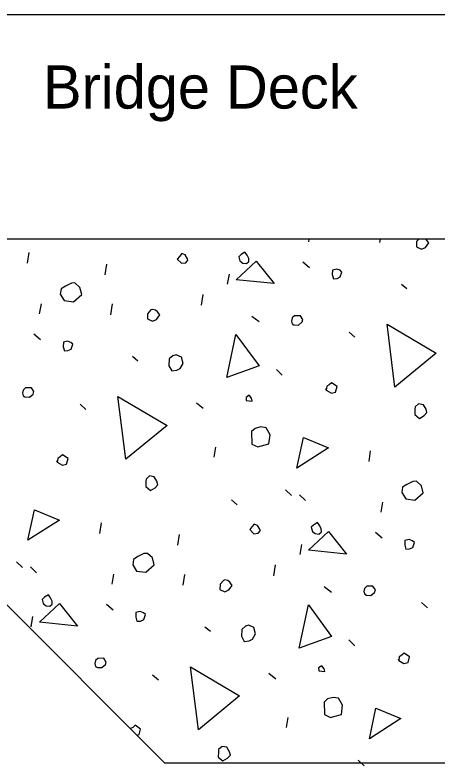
# Model space of a CAD drawing. Extents: x 112544 to 112597.1, y 111084 to 111107.1.
# Drawn here: x 112566.094 to 112567.572, y 111102.745 to 111105.363 of the extents above; entities that cross this region are included whole.
import ezdxf

# ---------------------------------------------------------------- set-up
doc = ezdxf.new("R2010")
doc.units = 0
for name, color, linetype in [('ActivePts-ConstElements', 7, 'Continuous'), ('Miscellaneous', 7, 'Continuous'), ('SupstrConc', 7, 'Continuous'), ('TextStructures', 7, 'Continuous')]:
    doc.layers.add(name, color=color, linetype=linetype)

msp = doc.modelspace()

# ---------------------------------------------------------------- linework, layer by layer
at = {"layer": 'ActivePts-ConstElements'}
msp.add_lwpolyline([(112543.9918, 111085.9039), (112574.7797, 111085.9039), (112574.7797, 111105.3634), (112543.9918, 111105.3634)], close=True, dxfattribs=at)
at = {"layer": 'Miscellaneous'}
for p, q in [((112567.1223, 111104.5697), (112567.1239, 111104.5786)), ((112567.3716, 111104.5666), (112567.3734, 111104.5786)), ((112566.1382, 111104.4949), (112566.1436, 111104.5326)), ((112567.1023, 111104.4996), (112567.1257, 111104.48)), ((112566.4105, 111104.454), (112566.416, 111104.4917)), ((112566.8386, 111104.4212), (112566.8447, 111104.4565)), ((112567.4469, 111104.4211), (112567.4665, 111104.4057)), ((112566.7471, 111104.3475), (112566.7525, 111104.3852)), ((112566.1806, 111104.3174), (112566.1866, 111104.3526)), ((112566.4299, 111104.3143), (112566.4353, 111104.352)), ((112566.923, 111104.3092), (112566.9488, 111104.2903)), ((112566.1605, 111104.2473), (112566.1839, 111104.2277)), ((112567.2641, 111104.2531), (112567.2844, 111104.2353)), ((112566.5051, 111104.1688), (112566.5247, 111104.1534)), ((112567.0092, 111104.1227), (112567.0301, 111104.1024)), ((112566.3223, 111104.0008), (112566.3427, 111103.9829)), ((112566.7298, 111104.0064), (112566.7531, 111103.9868)), ((112566.7912, 111103.8158), (112566.7973, 111103.8511)), ((112567.3336, 111103.8007), (112567.339, 111103.8384)), ((112567.0417, 111103.7018), (112567.0627, 111103.6815)), ((112567.0906, 111103.6838), (112567.1115, 111103.6635)), ((112566.8519, 111103.6664), (112566.8722, 111103.6486)), ((112567.376, 111103.6231), (112567.3821, 111103.6584)), ((112566.3918, 111103.5483), (112566.3972, 111103.586)), ((112567.3559, 111103.553), (112567.3793, 111103.5334)), ((112566.6642, 111103.5074), (112566.6696, 111103.5451)), ((112567.0923, 111103.4746), (112567.0983, 111103.5099)), ((112566.1, 111103.4494), (112566.1209, 111103.4292)), ((112566.1488, 111103.4315), (112566.1697, 111103.4112)), ((112567.0007, 111103.4009), (112567.0061, 111103.4386)), ((112566.4342, 111103.3708), (112566.4403, 111103.406)), ((112566.6835, 111103.3677), (112566.6889, 111103.4054)), ((112567.1766, 111103.3626), (112567.2024, 111103.3437)), ((112566.4142, 111103.3007), (112566.4375, 111103.2811)), ((112567.5178, 111103.3065), (112567.5381, 111103.2887)), ((112566.1505, 111103.2223), (112566.1566, 111103.2575)), ((112566.7587, 111103.2222), (112566.7784, 111103.2068)), ((112567.2628, 111103.1761), (112567.2838, 111103.1558)), ((112566.576, 111103.0542), (112566.5963, 111103.0363)), ((112566.9834, 111103.0598), (112567.0068, 111103.0402)), ((112567.0448, 111102.8692), (112567.0509, 111102.9045)), ((112567.2954, 111102.7552), (112567.3163, 111102.7349))]:
    msp.add_line(p, q, dxfattribs=at)
for points in [[(112567.5001, 111104.57), (112567.4998, 111104.5518), (112567.5176, 111104.5436), (112567.5314, 111104.5499), (112567.5427, 111104.5659), (112567.5346, 111104.5767), (112567.5324, 111104.5786)], [(112567.5077, 111104.5786), (112567.5001, 111104.57)], [(112566.6625, 111104.5086), (112566.6767, 111104.4943), (112566.6918, 111104.4958), (112566.6995, 111104.5056), (112566.6982, 111104.5104), (112566.6895, 111104.5236), (112566.6779, 111104.5283), (112566.6702, 111104.5184), (112566.6625, 111104.5086)], [(112566.8815, 111104.5026), (112566.8913, 111104.4949), (112566.9047, 111104.4933), (112566.9131, 111104.5007), (112566.9129, 111104.511), (112566.9073, 111104.5224), (112566.8992, 111104.5332), (112566.886, 111104.5245), (112566.8776, 111104.5171), (112566.8815, 111104.5026)], [(112566.8681, 111104.4369), (112566.9385, 111104.5023), (112567.0011, 111104.4233), (112566.8681, 111104.4369)], [(112567.2049, 111104.4547), (112567.2088, 111104.4402), (112567.2215, 111104.441), (112567.233, 111104.4467), (112567.2387, 111104.4637), (112567.232, 111104.4697), (112567.2204, 111104.4743), (112567.2059, 111104.4705), (112567.2049, 111104.4547)], [(112566.2528, 111104.3859), (112566.2665, 111104.3637), (112566.2987, 111104.3594), (112566.328, 111104.3853), (112566.3215, 111104.4095), (112566.3043, 111104.4256), (112566.2916, 111104.4248), (112566.2711, 111104.4141), (112566.2555, 111104.4047), (112566.2528, 111104.3859)], [(112566.5584, 111104.3177), (112566.5581, 111104.2995), (112566.5758, 111104.2913), (112566.5896, 111104.2976), (112566.6009, 111104.3135), (112566.5928, 111104.3243), (112566.586, 111104.3303), (112566.5751, 111104.3325), (112566.5703, 111104.3312), (112566.5584, 111104.3177)], [(112567.0647, 111104.2825), (112567.0708, 111104.279), (112567.0866, 111104.278), (112567.0992, 111104.2892), (112567.1021, 111104.2977), (112567.0933, 111104.3109), (112567.0727, 111104.3105), (112567.0644, 111104.3031), (112567.0621, 111104.2922), (112567.0647, 111104.2825)], [(112567.4244, 111104.0605), (112567.3965, 111104.2808), (112567.5686, 111104.1794), (112567.4244, 111104.0605)], [(112566.8356, 111104.0943), (112566.8676, 111104.2452), (112566.9489, 111104.135), (112566.8356, 111104.0943)], [(112566.2632, 111104.2023), (112566.267, 111104.1878), (112566.2798, 111104.1887), (112566.2912, 111104.1943), (112566.297, 111104.2114), (112566.2902, 111104.2173), (112566.2786, 111104.222), (112566.2641, 111104.2181), (112566.2632, 111104.2023)], [(112566.6344, 111104.1594), (112566.633, 111104.1358), (112566.643, 111104.1177), (112566.6605, 111104.1199), (112566.672, 111104.1255), (112566.6826, 111104.1439), (112566.6767, 111104.1656), (112566.659, 111104.1738), (112566.647, 111104.1706), (112566.6344, 111104.1594)], [(112567.1838, 111104.0504), (112567.2022, 111104.0398), (112567.2167, 111104.0437), (112567.2218, 111104.0632), (112567.2028, 111104.0762), (112567.1944, 111104.0688), (112567.1854, 111104.0638), (112567.1838, 111104.0504), (112567.1825, 111104.0553)], [(112566.1229, 111104.0302), (112566.1291, 111104.0266), (112566.1448, 111104.0257), (112566.1574, 111104.0368), (112566.1603, 111104.0453), (112566.1516, 111104.0585), (112566.131, 111104.0582), (112566.1226, 111104.0508), (112566.1203, 111104.0398), (112566.1229, 111104.0302)], [(112566.4826, 111103.8082), (112566.4547, 111104.0285), (112566.6268, 111103.9271), (112566.4826, 111103.8082)], [(112566.9037, 111104.0142), (112566.9249, 111104.0121), (112566.9223, 111104.0218), (112566.9143, 111104.0326), (112566.9035, 111104.0245), (112566.9037, 111104.0142)], [(112567.4942, 111103.9835), (112567.4939, 111103.9653), (112567.5105, 111103.9516), (112567.5262, 111103.961), (112567.5363, 111103.9715), (112567.5331, 111103.9835), (112567.5237, 111103.9992), (112567.5073, 111104.0025), (112567.4947, 111103.9914), (112567.4942, 111103.9835)], [(112566.9225, 111103.9053), (112566.9238, 111103.8617), (112566.9446, 111103.8518), (112566.9567, 111103.855), (112566.9832, 111103.8621), (112566.9876, 111103.8943), (112566.9732, 111103.9189), (112566.9544, 111103.9217), (112566.935, 111103.9165), (112566.9225, 111103.9053)], [(112567.0811, 111103.777), (112567.1042, 111103.8841), (112567.1915, 111103.848), (112567.0811, 111103.777)], [(112566.2421, 111103.7981), (112566.2604, 111103.7875), (112566.2749, 111103.7914), (112566.2801, 111103.8109), (112566.261, 111103.8239), (112566.2527, 111103.8165), (112566.2437, 111103.8115), (112566.2421, 111103.7981), (112566.2408, 111103.8029)], [(112566.5525, 111103.7311), (112566.5522, 111103.7129), (112566.5688, 111103.6993), (112566.5844, 111103.7086), (112566.5945, 111103.7191), (112566.5913, 111103.7312), (112566.5819, 111103.7468), (112566.5655, 111103.7502), (112566.5529, 111103.739), (112566.5525, 111103.7311)], [(112567.4482, 111103.6916), (112567.4619, 111103.6694), (112567.4941, 111103.6651), (112567.5234, 111103.6911), (112567.5169, 111103.7152), (112567.4997, 111103.7313), (112567.487, 111103.7305), (112567.4665, 111103.7198), (112567.4509, 111103.7105), (112567.4482, 111103.6916)], [(112566.1393, 111103.5247), (112566.1624, 111103.6318), (112566.2497, 111103.5957), (112566.1393, 111103.5247)], [(112566.9161, 111103.562), (112566.9303, 111103.5477), (112566.9455, 111103.5492), (112566.9532, 111103.559), (112566.9519, 111103.5638), (112566.9432, 111103.577), (112566.9316, 111103.5817), (112566.9239, 111103.5718), (112566.9161, 111103.562)], [(112567.1352, 111103.556), (112567.145, 111103.5483), (112567.1584, 111103.5467), (112567.1667, 111103.5541), (112567.1665, 111103.5644), (112567.1609, 111103.5758), (112567.1528, 111103.5866), (112567.1396, 111103.5779), (112567.1313, 111103.5705), (112567.1352, 111103.556)], [(112567.1217, 111103.4903), (112567.1922, 111103.5557), (112567.2547, 111103.4767), (112567.1217, 111103.4903)], [(112567.4586, 111103.5081), (112567.4625, 111103.4936), (112567.4752, 111103.4944), (112567.4866, 111103.5), (112567.4924, 111103.5171), (112567.4856, 111103.5231), (112567.474, 111103.5277), (112567.4595, 111103.5238), (112567.4586, 111103.5081)], [(112566.5064, 111103.4393), (112566.5201, 111103.4171), (112566.5524, 111103.4128), (112566.5816, 111103.4387), (112566.5752, 111103.4629), (112566.5579, 111103.479), (112566.5452, 111103.4781), (112566.5248, 111103.4675), (112566.5091, 111103.4581), (112566.5064, 111103.4393)], [(112566.812, 111103.3711), (112566.8117, 111103.3529), (112566.8294, 111103.3447), (112566.8433, 111103.351), (112566.8545, 111103.3669), (112566.8465, 111103.3777), (112566.8397, 111103.3836), (112566.8287, 111103.3859), (112566.8239, 111103.3846), (112566.812, 111103.3711)], [(112567.3184, 111103.3359), (112567.3245, 111103.3324), (112567.3403, 111103.3314), (112567.3528, 111103.3425), (112567.3557, 111103.3511), (112567.347, 111103.3643), (112567.3264, 111103.3639), (112567.318, 111103.3565), (112567.3158, 111103.3456), (112567.3184, 111103.3359)], [(112566.1934, 111103.3036), (112566.2032, 111103.2959), (112566.2166, 111103.2943), (112566.2249, 111103.3017), (112566.2248, 111103.3121), (112566.2191, 111103.3235), (112566.2111, 111103.3343), (112566.1979, 111103.3255), (112566.1895, 111103.3181), (112566.1934, 111103.3036)], [(112566.1799, 111103.2379), (112566.2504, 111103.3034), (112566.313, 111103.2244), (112566.1799, 111103.2379)], [(112567.0893, 111103.1477), (112567.1213, 111103.2986), (112567.2026, 111103.1884), (112567.0893, 111103.1477)], [(112566.5168, 111103.2557), (112566.5207, 111103.2412), (112566.5334, 111103.242), (112566.5448, 111103.2477), (112566.5506, 111103.2648), (112566.5438, 111103.2707), (112566.5322, 111103.2754), (112566.5177, 111103.2715), (112566.5168, 111103.2557)], [(112566.888, 111103.2128), (112566.8866, 111103.1892), (112566.8966, 111103.1711), (112566.9142, 111103.1733), (112566.9256, 111103.1789), (112566.9362, 111103.1973), (112566.9304, 111103.219), (112566.9127, 111103.2272), (112566.9006, 111103.224), (112566.888, 111103.2128)], [(112566.3766, 111103.0836), (112566.3827, 111103.08), (112566.3985, 111103.0791), (112566.411, 111103.0902), (112566.4139, 111103.0987), (112566.4052, 111103.1119), (112566.3846, 111103.1116), (112566.3762, 111103.1042), (112566.374, 111103.0932), (112566.3766, 111103.0836)], [(112567.4375, 111103.1038), (112567.4559, 111103.0932), (112567.4703, 111103.0971), (112567.4755, 111103.1166), (112567.4565, 111103.1296), (112567.4481, 111103.1222), (112567.4391, 111103.1172), (112567.4375, 111103.1038), (112567.4362, 111103.1087)], [(112566.7363, 111102.8616), (112566.7083, 111103.0819), (112566.8804, 111102.9805), (112566.7363, 111102.8616)], [(112567.1573, 111103.0676), (112567.1786, 111103.0655), (112567.176, 111103.0752), (112567.1679, 111103.086), (112567.1571, 111103.0779), (112567.1573, 111103.0676)], [(112567.1761, 111102.9587), (112567.1775, 111102.9151), (112567.1983, 111102.9051), (112567.2103, 111102.9084), (112567.2369, 111102.9155), (112567.2412, 111102.9477), (112567.2268, 111102.9723), (112567.208, 111102.975), (112567.1887, 111102.9699), (112567.1761, 111102.9587)], [(112567.3347, 111102.8304), (112567.3578, 111102.9375), (112567.4451, 111102.9014), (112567.3347, 111102.8304)], [(112566.5214, 111102.8428), (112566.5286, 111102.8448), (112566.5337, 111102.8642), (112566.5147, 111102.8773), (112566.5063, 111102.8699), (112566.4987, 111102.8656)], [(112566.8061, 111102.7845), (112566.8058, 111102.7663), (112566.8224, 111102.7527), (112566.838, 111102.762), (112566.8482, 111102.7725), (112566.8449, 111102.7846), (112566.8356, 111102.8002), (112566.8191, 111102.8036), (112566.8066, 111102.7924), (112566.8061, 111102.7845)]]:
    msp.add_lwpolyline(points, dxfattribs=at)
at = {"layer": 'SupstrConc'}
for p, q in [((112569.7858, 111104.5786), (112565.0089, 111104.5786)), ((112566.6191, 111102.7453), (112565.7441, 111103.6203)), ((112569.5063, 111102.7453), (112566.6191, 111102.7453))]:
    msp.add_line(p, q, dxfattribs=at)

# ---------------------------------------------------------------- texts
at = {"layer": 'TextStructures'}
msp.add_text('Bridge Deck', height=0.1512, dxfattribs=at).set_placement((112566.1926, 111105.0358))

doc.saveas('drawing.dxf')
